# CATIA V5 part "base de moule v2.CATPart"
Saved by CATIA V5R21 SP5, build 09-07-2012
Part number: base de moule v2
Bounding box of the stored display mesh (mm): x -124.81 to 134.81, y -84.81 to 84.81, z -5 to 61.5
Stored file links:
  \\salsa.univ-amu.fr\dfs\myhome_etud\DOSSIERS_WINDOWS\Documents\stage s4\CAO\base de moule v2.CATPart
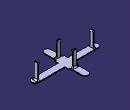
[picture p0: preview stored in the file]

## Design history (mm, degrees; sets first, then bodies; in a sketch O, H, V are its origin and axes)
Body1 (main body)
  Sketch1 on xy-plane, origin (0, 0, 0), H (1, 0, 0), V (0, 1, 0)
    line L1 (-112.5, 12.5) -> (-12.5, 12.5)
    line L2 (-12.5, 12.5) -> (-12.5, 72.5)
    line L3 (12.5, 72.5) -> (12.5, 12.5)
    line L4 (12.5, 12.5) -> (122.5, 12.5)
    line L5 (122.5, -12.5) -> (12.5, -12.5)
    line L6 (12.5, -12.5) -> (12.5, -72.5)
    line L7 (-12.5, -72.5) -> (-12.5, -12.5)
    line L8 (-12.5, -12.5) -> (-112.5, -12.5)
    arc A1 centre (0, -72.5) radius 12.5 from (-12.5, -72.5) to (12.5, -72.5) ccw
    point P14 (71, 0)
    arc A2 centre (0, 72.5) radius 12.5 from (12.5, 72.5) to (-12.5, 72.5) ccw
    point P15 (0, 72.5)
    point P16 (12.5, 72.5)
    arc A3 centre (122.5, 0) radius 12.5 from (122.5, -12.5) to (122.5, 12.5) ccw
    point P18 (122.5, 0)
    arc A4 centre (-112.5, 0) radius 12.5 from (-112.5, 12.5) to (-112.5, -12.5) ccw
    point P20 (-112.5, 0)
    distance L4 L5 = 25
    distance L8 L1 = 25
    distance L6 L7 = 25
    distance L3 L2 = 25
    radius A1 = 12.5
    length L6 = 60
    length L4 = 110
    length L5 = 110
    length L1 = 100
    length L8 = 100
    length L3 = 60
    length L2 = 60
    distance A2 A1 = 170
    horizontal: L1 H, L4 H, L5 H, L8 H
    vertical: L2 V, L3 V, L6 V, L7 V
    symmetry: L5 L4 H, L8 L1 H, L6 L7 V, L3 L2 V
    tangency: A1 L2, A2 L3, A3 L4, A4 L1
    coincidence: P14 H, P15 V, P16 L3, P18 H, P20 H
  Pad1: profile Sketch1, direction (0, 0, 1), length 1.5, mirrored extent
  Sketch2 on end face of Pad1, origin (0, 0, 1.5), H (1, 0, 0), V (0, 1, 0)
    line L1 (-18.5, 26.5) -> (18.5, 26.5)
    line L2 (18.5, 26.5) -> (18.5, -26.5)
    line L3 (18.5, -26.5) -> (-18.5, -26.5)
    line L4 (-18.5, -26.5) -> (-18.5, 26.5)
    distance L2 L4 = 37
    distance L3 L1 = 53
    horizontal: L1 H, L3 H
    vertical: L2 V, L4 V
    symmetry: L2 L4 V, L3 L1 H
  Pad2: profile Sketch2, direction (0, 0, -1), length 2
  Sketch3 on start face of Pad1, origin (0, 0, -1.5), H (1, 0, 0), V (0, -1, 0)
    line L1 (67.3, 4.05) -> (74.7, 4.05)
    line L2 (74.7, 4.05) -> (74.7, 1.25)
    line L3 (74.7, 1.25) -> (67.3, 1.25)
    line L4 (67.3, 1.25) -> (67.3, 4.05)
    point P5 (67.3, -1.25)
    line L5 (67.3, -1.25) -> (74.7, -1.25)
    line L6 (74.7, -1.25) -> (74.7, -4.05)
    line L7 (74.7, -4.05) -> (67.3, -4.05)
    line L8 (67.3, -4.05) -> (67.3, -1.25)
    point P7 (74.7, -4.05)
    point P9 (-38.1, -1.25)
    line L9 (-38.1, -1.25) -> (-30.7, -1.25)
    line L10 (-30.7, -1.25) -> (-30.7, -4.05)
    line L11 (-30.7, -4.05) -> (-38.1, -4.05)
    line L12 (-38.1, -4.05) -> (-38.1, -1.25)
    point P11 (-30.7, -4.05)
    point P13 (-30.7, 1.25)
    line L13 (-30.7, 1.25) -> (-38.1, 1.25)
    line L14 (-38.1, 1.25) -> (-38.1, 4.05)
    line L15 (-38.1, 4.05) -> (-30.7, 4.05)
    line L16 (-30.7, 4.05) -> (-30.7, 1.25)
    point P15 (-38.1, 4.05)
    line L17 (-3.7, -66) -> (3.7, -66)
    line L18 (3.7, -66) -> (3.7, -68.8)
    line L19 (3.7, -68.8) -> (-3.7, -68.8)
    line L20 (-3.7, -68.8) -> (-3.7, -66)
    point P21 (-3.7, -71.3)
    line L21 (-3.7, -71.3) -> (3.7, -71.3)
    line L22 (3.7, -71.3) -> (3.7, -74.1)
    line L23 (3.7, -74.1) -> (-3.7, -74.1)
    line L24 (-3.7, -74.1) -> (-3.7, -71.3)
    point P23 (3.7, -74.1)
    point P25 (3.7, 66)
    line L25 (3.7, 66) -> (-3.7, 66)
    line L26 (-3.7, 66) -> (-3.7, 68.8)
    line L27 (-3.7, 68.8) -> (3.7, 68.8)
    line L28 (3.7, 68.8) -> (3.7, 66)
    point P27 (-3.7, 68.8)
    point P29 (3.7, 74.1)
    line L29 (3.7, 74.1) -> (-3.7, 74.1)
    line L30 (-3.7, 74.1) -> (-3.7, 71.3)
    line L31 (-3.7, 71.3) -> (3.7, 71.3)
    line L32 (3.7, 71.3) -> (3.7, 74.1)
    point P31 (-3.7, 71.3)
    distance L16 L4 = 98
    distance L3 L5 = 2.5
    distance H L17 = 66
    distance H L25 = 66
    distance L27 L31 = 2.5
    distance L19 L21 = 2.5
    length L23 = 7.4
    length L24 = 2.8
    length L20 = 2.8
    length L30 = 2.8
    length L28 = 2.8
    length L6 = 2.8
    length L1 = 7.4
    length L2 = 2.8
    length L11 = 7.4
    distance L16 L26 = 27
    horizontal: L1 H, L3 H, L5 H, L7 H, L9 H, L11 H, L13 H, L15 H, L17 H, L19 H, L21 H, L23 H, L25 H, L27 H, L29 H, L31 H
    vertical: L2 V, L4 V, L6 V, L8 V, L10 V, L12 V, L14 V, L16 V, L18 V, L20 V, L22 V, L24 V, L26 V, L28 V, L30 V, L32 V
    coincidence: P5 L4, P7 L2, P9 L5, P11 L7, P13 L10, P13 L3, P15 L12, P15 L1, P21 L20, P23 L18, P25 L18, P27 L20, P29 L28, P31 L26
    symmetry: L18 L20 V, L26 L28 V, L3 L5 H
  Pad3: profile Sketch3, direction (0, 0, -1), length 3.5
  Sketch4 on face of Pad2, origin (0, 0, 1.5), H (1, 0, 0), V (0, 1, 0)
    line L1 (-103, 6) -> (-99, 6)
    line L2 (-99, 6) -> (-99, -6)
    line L3 (-99, -6) -> (-103, -6)
    line L4 (-103, -6) -> (-103, 6)
    point P5 (115, -6)
    line L5 (115, -6) -> (119, -6)
    line L6 (119, -6) -> (119, 6)
    line L7 (119, 6) -> (115, 6)
    line L8 (115, 6) -> (115, -6)
    point P7 (119, 6)
    line L9 (-6, -29.5) -> (6, -29.5)
    line L10 (6, -29.5) -> (6, -33.5)
    line L11 (6, -33.5) -> (-6, -33.5)
    line L12 (-6, -33.5) -> (-6, -29.5)
    point P13 (-6, 29.5)
    line L13 (-6, 29.5) -> (6, 29.5)
    line L14 (6, 29.5) -> (6, 33.5)
    line L15 (6, 33.5) -> (-6, 33.5)
    line L16 (-6, 33.5) -> (-6, 29.5)
    point P15 (6, 33.5)
    distance V L2 = 99
    distance V L8 = 115
    distance H L9 = 29.5
    length L11 = 12
    length L10 = 4
    length L14 = 4
    length L5 = 4
    length L3 = 4
    length L6 = 12
    horizontal: L1 H, L3 H, L5 H, L7 H, L9 H, L11 H, L13 H, L15 H
    vertical: L2 V, L4 V, L6 V, L8 V, L10 V, L12 V, L14 V, L16 V
    coincidence: P5 L3, P7 L1, P13 L12, P15 L10
    symmetry: L9 L13 H, L12 L10 V, L5 L7 H
  Pad4: profile Sketch4, direction (0, 0, 1), length 60
  Sketch5 on face of Pad4 from Sketch4.L5, origin (0, -6, 0), H (1, 0, 0), V (0, 0, 1)
    line L1 (115, 61.5) -> (114.9, 61.5)
    line L2 (114.9, 56.5) -> (115, 56.5)
    line L3 (115, 56.5) -> (115, 61.5)
    reference projected line E1 (12.5, 1.5) -> (122.5, 1.5) from edge [face of Pad1 from Sketch1.L5 | face of Pad2]
    reference projected line E2 (119, 1.5) -> (119, 61.5) from edge [face of Pad4 from Sketch4.L6 | face of Pad4 from Sketch4.L5]
    arc A1 centre (114.9, 59) radius 2.5 from (114.9, 56.5) to (114.9, 61.5) cw
    line L4 (-99, 61.5) -> (-98.9, 61.5)
    line L5 (-98.9, 56.5) -> (-99, 56.5)
    line L6 (-99, 56.5) -> (-99, 61.5)
    reference projected line E3 (-112.5, 1.5) -> (-12.5, 1.5) from edge [face of Pad1 from Sketch1.L8 | face of Pad2]
    reference projected line E4 (-103, 1.5) -> (-103, 61.5) from edge [face of Pad4 from Sketch4.L3 | face of Pad4 from Sketch4.L4]
    arc A2 centre (-98.9, 59) radius 2.5 from (-98.9, 61.5) to (-98.9, 56.5) cw
    distance L2 E1 = 55
    length L3 = 5
    distance L3 E2 = 4
    distance L5 E3 = 55
    length L6 = 5
    distance L6 E4 = 4
    length L1 = 0.1
    length L2 = 0.1
    length L4 = 0.1
    radius A2 = 2.5
    horizontal: L1 H, L2 H, L4 H, L5 H
    tangency: A1 L1, A2 L4
    vertical: L6 V
  Pad5: profile Sketch5, direction (0, 1, 0), length 12
  Sketch6 on face of Pad4 from Sketch4.L16, origin (-6, 0, 0), H (0, -1, 0), V (0, 0, 1)
    line L1 (-29.5, 61.5) -> (-29.3, 61.5)
    line L2 (-29.3, 56.5) -> (-29.5, 56.5)
    line L3 (-29.5, 56.5) -> (-29.5, 61.5)
    reference projected line E1 (-72.5, 1.5) -> (-12.5, 1.5) from edge [face of Pad1 from Sketch1.L2 | face of Pad2]
    reference projected line E2 (-33.5, 1.5) -> (-33.5, 61.5) from edge [face of Pad4 from Sketch4.L16 | face of Pad4 from Sketch4.L15]
    arc A1 centre (-29.3, 59) radius 2.5 from (-29.3, 56.5) to (-29.3, 61.5) ccw
    line L4 (29.5, 61.5) -> (29.3, 61.5)
    line L5 (29.3, 56.5) -> (29.5, 56.5)
    line L6 (29.5, 56.5) -> (29.5, 61.5)
    reference projected line E3 (12.5, 1.5) -> (72.5, 1.5) from edge [face of Pad1 from Sketch1.L7 | face of Pad2]
    reference projected line E4 (33.5, 1.5) -> (33.5, 61.5) from edge [face of Pad4 from Sketch4.L11 | face of Pad4 from Sketch4.L12]
    arc A2 centre (29.3, 59) radius 2.5 from (29.3, 61.5) to (29.3, 56.5) ccw
    distance L2 E1 = 55
    length L3 = 5
    distance L3 E2 = 4
    length L1 = 0.2
    radius A1 = 2.5
    distance L5 E3 = 55
    length L6 = 5
    distance L6 E4 = 4
    radius A2 = 2.5
    length L4 = 0.2
    horizontal: L1 H, L2 H, L4 H, L5 H
    vertical: L3 V, L6 V
    tangency: A1 L2, A2 L4
  Pad6: profile Sketch6, direction (1, 0, 0), length 12
  Fillet1: radius 5, on edge [face of Pad2 | face of Pad4 from Sketch4.L6]
  Fillet2: radius 5, on edge [face of Pad5 | face of Pad2]
  Fillet3: radius 5, on edge [face of Pad5 | face of Pad2]
  Fillet4: radius 5, on edge [face of Pad2 | face of Pad4 from Sketch4.L15]; edge [face of Pad2 | face of Pad6] (x4); edge [face of Pad2 | face of Pad5] (x2); edge [face of Pad2 | face of Pad4 from Sketch4.L4]; edge [face of Pad2 | face of Pad4 from Sketch4.L11]
  Chamfer1: length 1, angle 45, on edge [face of Pad4 from Sketch4.L11 | face of Pad6]; edge [face of Pad4 from Sketch4.L6 | face of Pad5]; edge [face of Pad4 from Sketch4.L15 | face of Pad6]; edge [face of Pad4 from Sketch4.L4 | face of Pad5]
